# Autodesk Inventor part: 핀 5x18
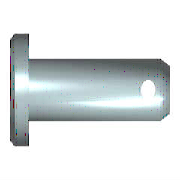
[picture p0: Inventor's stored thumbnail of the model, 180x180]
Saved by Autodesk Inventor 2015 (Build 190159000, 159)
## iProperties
Created: 2012-02
Part Number: 핀 5x18
Material: 강철
Description: 머리가 있는 클레비스 핀
Document SubType Name: Modeling
Standard: ISO 2341
Designer: test
Standard Revision: Second edition 1986-11-01
Standards Organization: ISO
Language: ko-KR
Size Designation: B - 5 x 18
Categories: <MemberInstance><Categories><Category DisplayName="조임쇠" InternalName="e4da775c-781d-43d5-af7c-5136215cf5a6" Mnemonic="FSTN"><Category DisplayName="핀" InternalNa
Density: 7.85 g/cm^3
Appearance: 주황색
IsCustomPart: 1
Author: test
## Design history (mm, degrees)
sketch "스케치1"
  geometry: L1 (-1.6, 0)-(-1.6, 4); L2 (-1.6, 4)-(0, 4); L3 (0, 4)-(0, 2.5); L4 (0, 2.5)-(18, 2.5); L5 (18, 2.5)-(18, 0); L6 (-1.6, 0)-(18, 0); L7 (-5.52, 0)-(21.92, 0) reference; L8 (0, -2.414)-(0, 5.069) reference; C1 r 0.6 at (15.1, 0)
  constraints: 12 end point, 3 parallel, 2 collinear, 2 perpendicular, 1 centre point, 1 point on line, 1 vertical
  dimensions: "d0" = 5 diameter of L4 L6 (= NND); "d1" = 8 diameter of L2 L6 (= KOD); "d2" = 1.6 distance of L1.end L2.end (= KOH); "d3" = 18 distance of L3.end L4.end (= NLG); "d5" = 2.9 distance from line of L5 C1.centre (= DIST); "d6" = 1.2 diameter of C1 (= BOR)
revolve "본체" stored, may be unused: angle "d4" = 90 deg
extrude "구멍" cut sketch "스케치1" stored distance "d7" = 5 (= NND); taper "d8" = 0 deg
workaxis "Work Axis1"
workplane "Work Plane1"
node "작업 평면5"
  node "작업 평면4"
sketch "스케치2"
  geometry: C1 r 1.345 at (0, 0) reference
body "Solid1"
chamfer "모따기1" distance "d9" = 1 (= PHH2); stored, may be unused: angle "d10" = 45 deg (= FAWI2), second distance "d16" = 1 (= PHH2)
chamfer "모따기2" distance "d11" = 2 (= PHH1); stored, may be unused: angle "d12" = 30 deg (= FAWI1), second distance "d17" = 2 (= PHH1)
other parameters: "PHH1" = 2 [user parameter; used in 2 equation terms], "PHH2" = 1 [user parameter; used in 2 equation terms], "KOD" = 8 [user parameter; used in 1 equation term], "KOH" = 1.6 [user parameter; used in 1 equation term], "NND" = 5 [user parameter; used in 2 equation terms], "FAWI1" = 30 deg [user parameter; used in 1 equation term], "FAWI2" = 45 deg [user parameter; used in 1 equation term], "DIST" = 2.9 [user parameter; used in 1 equation term], "BOR" = 1.2 [user parameter; used in 1 equation term], "NLG" = 18 [user parameter; used in 1 equation term], "d13" = 0, "d14" = 0, "d27" = 0, "d28" = 0, "d29" = 0, "d30" = 0, "d31" = 0
